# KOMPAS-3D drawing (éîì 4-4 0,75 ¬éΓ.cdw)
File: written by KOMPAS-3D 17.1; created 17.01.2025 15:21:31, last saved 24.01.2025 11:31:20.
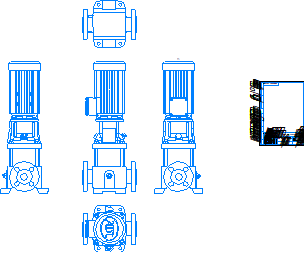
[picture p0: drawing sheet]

Sheet 1: A4, portrait

Title block, sheet 1: name: ВМН 4-4 0,75 кВт; designation: ВМН 4-4 0,75 кВт; sheets: 1; sheet format: A4; stored path: \\adlc.lan\data\АДЛ_ПКД\3D-модели\ADL production\Насосы ГРАНПАМП\Насосы ВМН\ВМН4\KOMPAS 2D\ВМН 4-4 0,75 кВт.cdw

Views: Вид 1, Спереди, Проекционный вид 2, Проекционный вид 3, Проекционный вид 4, Проекционный вид 5
Referenced files in \\adlc.lan\data\АДЛ_ПКД\3D-модели\ADL production\Насосы ГРАНПАМП\Насосы ВМН\ВМН4\KOMPAS 3D\: ВМН 4-4-0,75 кВт.m3d
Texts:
  Andrey
  АДЛ
Dimensions and other numbers on the sheet: 1:1; 1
